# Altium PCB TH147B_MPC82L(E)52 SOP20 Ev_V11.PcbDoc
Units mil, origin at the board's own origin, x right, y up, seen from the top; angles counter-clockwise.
Board outline 2850 x 2110 mil, 2 copper layers (Top Layer, Bottom Layer); 44 components, 39 nets, 228 pads, 82 vias.
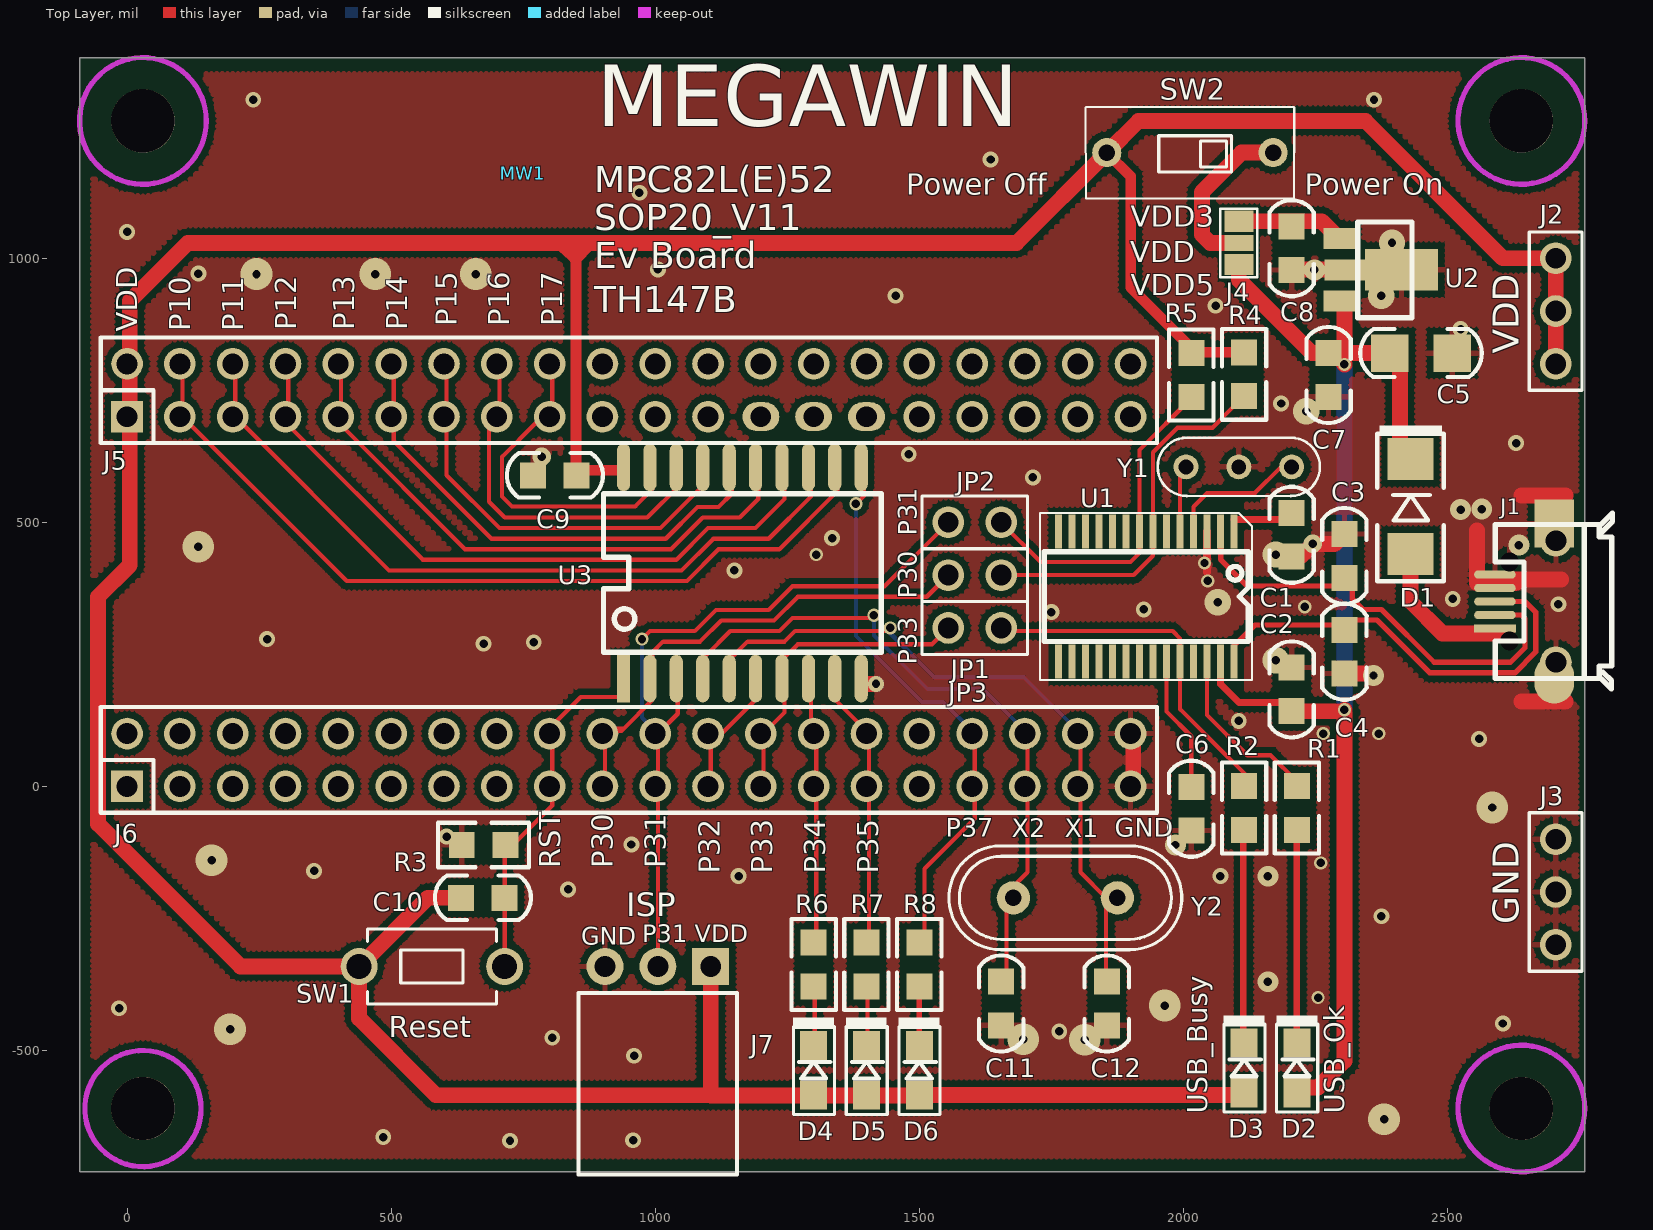
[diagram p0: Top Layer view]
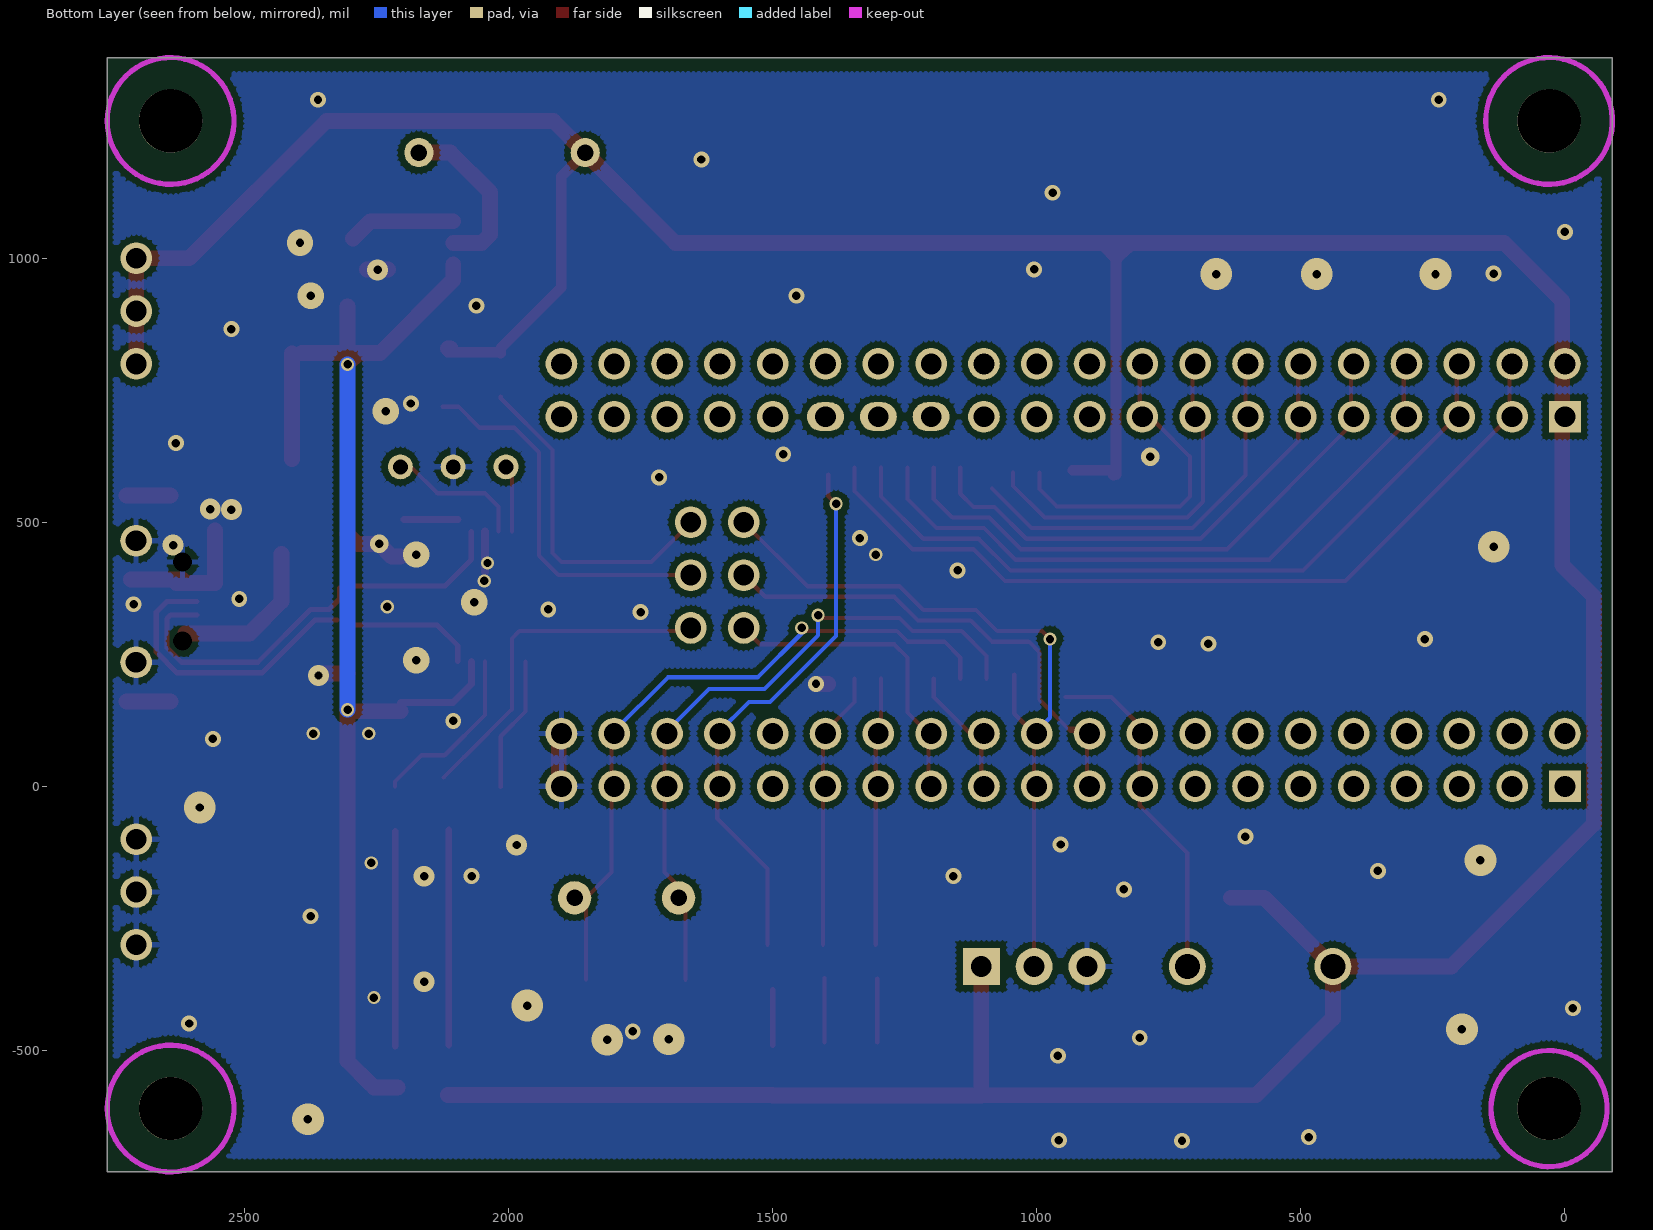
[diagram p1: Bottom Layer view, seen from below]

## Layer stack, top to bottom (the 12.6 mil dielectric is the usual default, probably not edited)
Top Layer: signal copper 1.4
Dielectric: dielectric 12.6, FR-4, Dk 4.8
Bottom Layer: signal copper 1.4

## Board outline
-90,-730 -90,1380 2760,1380 2760,-730

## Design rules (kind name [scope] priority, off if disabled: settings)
Clearance 12 [All] p1 off: gap=12
Clearance 10 [All] p2 off: gap=10
Clearance 6 [All] p3: gap=6
ComponentClearance [All] p1 off: gap=10 collisioncheckmode=3 verticalgap=10 showdistances=FALSE
HoleSize [All] p1: absolutevalues=TRUE maxlimit=500 minlimit=1 maxpercent=80.000 minpercent=20.000
MinimumSolderMaskSliver [All] p1 off: minsoldermaskwidth=10
PolygonConnect VIA [ISVIA] p1: connectstyle=Direct reliefconductorwidth=10 reliefentries=4 polygonreliefangle="90 Angle"
PolygonConnect [All] p2: connectstyle=Relief reliefconductorwidth=10 reliefentries=4 polygonreliefangle="90 Angle"
RoomDefinition "TH147B_MPC82L(E)52 SOP20 Ev_V10" [InComponentClass('TH147B_MPC82L(E)52 SOP20 Ev_V10')] p1: confinementstyle=ConfineIn formatcopy=TRUE lockcomponents=FALSE outline -465,-1240 3115,-1240 3115,1670 -465,1670
RoutingVias [All] p1: holewidth=16 width=25 viastyle="Through Hole" minholewidth=16 minwidth=24 maxholewidth=28 maxwidth=50
SilkToSilkClearance [All] p1 off: silktosilkclearance=10
SilkscreenOverComponentPads [All] p1 off: minsilkscreentomaskgap=10
SolderMaskExpansion [All] p1 off: expansion=4
Width [All] p1: maxlimit=200 minlimit=6 preferedwidth=10
23 further rules are at their usual default settings.

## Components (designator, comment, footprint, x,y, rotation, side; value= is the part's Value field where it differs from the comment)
C1 "4.7uF" 0805C 2205,476.34 r270 top
C2 "0.1uF" 0805C 2205,183.66 r270 top
C3 "15pF" 0805C 2305,436.34 r90 top
C4 "15pF" 0805C 2305,255 r270 top
C5 "4.7uF" 1206C 2450,820.34 r0 top
C6 "0.1uF" 0805C 2015,-42.34 r90 top
C7 "0.1uF" 0805C 2275,779 r270 top
C8 "4.7uF" 0805C 2205,1019 r270 top
C9 "0.1uF" 0805C 810,589 r180 top
C10 "1u" 0805C 673.66,-211 r0 top
C11 "30p" 0805C 1655,-411 r270 top
C12 "30p" 0805C 1855,-411 r270 top
D1 "1N5817" D5817_SMD_1 2430,530 r270 top
D2 "Yellow" 0805D 2215,-533.08 r90 top
D3 "RED" 0805D 2115,-533.08 r90 top
D4 "Green" 0805D 1300,-537.34 r90 top
D5 "RED" 0805D 1400,-537.34 r90 top
D6 "Green" 0805D 1500,-537.34 r90 top
J1 "Micro USB母座" JACK_USB_SMD290X220P065 2590,350 r180 top
J2 "*" PS3P254 2705,800 r90 top
J3 "*" PS3P254 2705,-100 r270 top
J4 "*" JUMP3_SMD 2105,1029 r90 top
J5 "*" PS20X2P254#1 0,700 r0 top locked
J6 "*" PS20X2P254#2 0,0 r0 top locked
J7 "*" PS3P254f_90 1105,-341 r180 top
JP1 "JUMPER2" PS2P254 1555,400 r0 top
JP2 "JUMPER2" PS2P254 1555,500 r0 top
JP3 "JUMPER2" PS2P254 1555,300 r0 top
MW1 "MW-A4" MEGAWIN_T 749.19,1161.19 r0 top
R1 "1K" 0805R 2215,-41 r270 top
R2 "1K" 0805R 2115,-41 r270 top
R3 "47K" 0805R 675,-111 r0 top
R4 "4.7K" 0805R 2115,780.34 r270 top
R5 "4.7K" 0805R 2015,779 r270 top
R6 "1K" 0805R 1300,-337.34 r270 top
R7 "1K" 0805R 1400,-337.34 r270 top
R8 "1K" 0805R 1500,-337.34 r270 top
SW1 "SW TACT-SPST" SW_T_2P 577.21,-341 r180 top
SW2 "-" DIP2_SW 2170,1200 r180 top
U1 "MA101_TSSOP28" TSSOP28_170P065 1929.84,359.52 r180 top
U2 "AIC1734-33(SOT-89)" SOT89 2295,978.06 r270 top
U3 "MPC82L52(20-SOP)" SO20_300P127 1165,404 r0 top locked
Y1 "6MHz" X3P 2205,605 r180 top
Y2 "22.1184MHz" X49U 1776.57,-211 r0 top

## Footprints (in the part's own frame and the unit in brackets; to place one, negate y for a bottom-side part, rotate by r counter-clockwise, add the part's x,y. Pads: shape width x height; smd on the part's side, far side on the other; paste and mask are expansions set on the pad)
0805C [mm]
  rect 1.25x1.25 smd: 1(-1.05,0) 2(1.05,0)
  silkscreen extent -2.31,-1.07 2.31,1.07
0805D [mm]
  rect 1.4x1.3 smd: 1(-1.192,0) 2(1.192,0)
  silkscreen extent -2.12,-1 2.53,0.98
0805R [mm]
  rect 1.25x1.25 smd: 1(-1.05,0) 2(1.05,0)
  silkscreen extent -2.18,-1.07 2.18,1.07
1206C [mm]
  rect 1.8x1.8 smd: 1(-1.5,0) 2(1.5,0)
  silkscreen extent -2.92,-1.15 2.92,1.16
D5817_SMD_1 [mil]
  rect 80x86.61 smd: 1(90,0) 2(-90,0)
  silkscreen extent -153,-63 142,63
DIP2_SW [mm]
  round 1.4 hole 0.8: 1(0,0) 2(8,0)
  silkscreen extent -1.02,-2.2 9.02,2.2
JACK_USB_SMD290X220P065 [mm]
  rect 1.9x1.8 on Mech2: 0(-2.85,-1.15) 0(-2.85,1.15)
  round 0.8 hole 0.9 unplated: 1(-0.7,1.9) 5(-0.7,-1.9)
  rect 2x0.4 smd: 1(0,1.3)
  oval 2x0.4 smd: 2(0,0.65) 3(0,0) 4(0,-0.65) 5(0,-1.3)
  round 1.524 hole 1: 5(-2.931,2.921) 5(-2.931,-2.921)
  oval 1.9x2.3 smd: 5(-2.85,3.75)
  rect 1.9x2.3 smd: 5(-2.85,-3.75)
  silkscreen extent -5.65,-4.25 -0.01,4.2
JUMP3_SMD [mil]
  rect 40x55 smd: 1(-41,0) 3(41,0)
  rect 30x55 smd: 2(0,0)
  silkscreen extent -65,-35 65,35
MEGAWIN_T [mil]
PS2P254 [mil]
  round 60 hole 39.37: 1(0,0) 2(100,0)
  silkscreen extent -50,-50 150,50
PS3P254 [mil]
  round 60 hole 39.37: 1(0,0) 2(100,0) 3(200,0)
  silkscreen extent -50,-50 250,50
PS3P254f_90 [mil]
  rect 70x70 hole 39.37: 1(0,0)
  round 70 hole 39.37: 2(100,0) 3(200,0)
  silkscreen extent -50,50 250,394
PS20X2P254#1 [mil]
  rect 60x60 hole 39.37: 1(0,0)
  round 60 hole 39.37: 2(0,100) 3(100,0) 4(100,100) 5(200,0) 6(200,100) 7(300,0) 8(300,100) 9(400,0) 10(400,100) 11(500,0) 12(500,100) 13(600,0) 14(600,100) 15(700,0) 16(700,100) 17(800,0) 18(800,100) 19(900,0) 20(900,100) 21(1000,0) 22(1000,100) 23(1100,0) 24(1100,100) 26(1200,100) 28(1300,100) 30(1400,100) 31(1500,0) 32(1500,100) 33(1600,0) 34(1600,100) 35(1700,0) 36(1700,100) 37(1800,0) 38(1800,100) 39(1900,0) 40(1900,100)
  oval 70x55 hole 39.37: 25(1200,0) 27(1300,0) 29(1400,0)
  silkscreen extent -50,-50 1950,150
PS20X2P254#2 [mil]
  rect 60x60 hole 39.37: 1(0,0)
  round 60 hole 39.37: 2(0,100) 3(100,0) 4(100,100) 5(200,0) 6(200,100) 7(300,0) 8(300,100) 9(400,0) 10(400,100) 11(500,0) 12(500,100) 13(600,0) 14(600,100) 15(700,0) 16(700,100) 17(800,0) 18(800,100) 19(900,0) 20(900,100) 21(1000,0) 22(1000,100) 23(1100,0) 24(1100,100) 25(1200,0) 26(1200,100) 27(1300,0) 28(1300,100) 29(1400,0) 30(1400,100) 31(1500,0) 32(1500,100) 33(1600,0) 34(1600,100) 35(1700,0) 36(1700,100) 37(1800,0) 38(1800,100) 39(1900,0) 40(1900,100)
  silkscreen extent -50,-50 1950,150
SO20_300P127 [mil]
  rect 25x90 smd: 1(-225,-200)
  oval 25x90 smd: 2(-175,-200) 3(-125,-200) 4(-75,-200) 5(-25,-200) 6(25,-200) 7(75,-200) 8(125,-200) 9(175,-200) 10(225,-200) 11(225,200) 12(175,200) 13(125,200) 14(75,200) 15(25,200) 16(-25,200) 17(-75,200) 18(-125,200) 19(-175,200) 20(-225,200)
  silkscreen extent -263,-150 263,150
SOT89 [mm]
  rect 1.016x1.5 smd: 1(-1.5,0) 3(1.5,0)
  rect 2x3.5 smd: 2(0,3)
  rect 1.016x2.6 smd: 2(0,0.6)
  silkscreen extent -2.3,0.9 2.3,3.5
SW_T_2P [mil]
  round 70 hole 47.24: 1(-137.79,0) 2(137.79,0)
  silkscreen extent -122,-71 122,71
TSSOP28_170P065 [mil]
  rect 13x65 smd: 1(-166.34,-123) 2(-140.75,-123) 3(-115.16,-123) 4(-89.57,-123) 5(-63.98,-123) 6(-38.39,-123) 7(-12.79,-123) 8(12.8,-123) 9(38.39,-123) 10(63.98,-123) 11(89.57,-123) 12(115.16,-123) 13(140.75,-123) 14(166.34,-123) 15(166.34,123) 16(140.75,123) 17(115.16,123) 18(89.57,123) 19(63.98,123) 20(38.39,123) 21(12.8,123) 22(-12.79,123) 23(-38.39,123) 24(-63.98,123) 25(-89.57,123) 26(-115.16,123) 27(-140.75,123) 28(-166.34,123)
  silkscreen extent -200,-158 201,158
X3P [mm]
  round 1.2 hole 0.711: 1(0,0) 2(5.08,0) 3(2.54,0)
  silkscreen extent -1.36,-1.4 6.44,1.4
X49U [mm]
  round 1.6 hole 0.8: 1(-2.5,0) 2(2.5,0)
  silkscreen extent -5.6,-2.5 5.6,2.5

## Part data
C1 C5 C8: library part CAP
C2 C3 C4 C6 C7 C9: library part "CAP NP"
C10: library part C
C11 C12: library part "C NP"
D1: library part DIODE_ZD, "Schottky Diode"
D2 D3 D4 D5 D6: library part LED
J1: library part CON5, "Connector"
J2 J3 J4 J7: library part CON3
J5 J6: library part CON40A
R1 R2 R4 R5 R6 R7 R8: library part R_Dup1
R3: library part R
SW2: library part SW-2
U2: library part AIC1734-33(SOT-89)_0
U3: library part MPC82L52(20-DIP)
Y1: library part CRYSTAL_RC
Y2: library part CRYSTAL

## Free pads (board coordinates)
  round 120 hole 120 unplated: 0(30,-610) 0(30,1260) 0(2640,-610) 0(2640,1260)

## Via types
v1: diameter 30, hole 16, Top Layer to Bottom Layer, tented both sides, 41 vias
v2: diameter 25, hole 16, Top Layer to Bottom Layer, tented both sides, 14 vias
v3: diameter 60, hole 16, Top Layer to Bottom Layer, tented both sides, 11 vias
v4: diameter 50, hole 16, Top Layer to Bottom Layer, tented both sides, 6 vias
v5: diameter 39.37, hole 16, Top Layer to Bottom Layer, tented both sides, 5 vias
v6: diameter 40, hole 16, Top Layer to Bottom Layer, tented both sides, 3 vias
v7: diameter 35, hole 16, Top Layer to Bottom Layer, tented both sides, 2 vias

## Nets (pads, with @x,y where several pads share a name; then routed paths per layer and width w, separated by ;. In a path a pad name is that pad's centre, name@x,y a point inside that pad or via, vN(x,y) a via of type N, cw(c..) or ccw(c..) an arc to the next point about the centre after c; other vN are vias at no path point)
D+: C4.1 J1.3 U1.28 | length 815.5
  Top Layer w10: U1.28 2096.18,266.18 2135.67,305.67 C4.1@2305,305.67 ; C4.1@2325,315 2366.72,315 2466.72,215 2627.72,215 2667,254.28 2667,329.93 2646.93,350 J1.3
D-: C3.1 J1.2 U1.2 | length 831.4
  Top Layer w10: U1.2 2070.59,429.41 2120.63,379.37 C3.1@2305,379.37 ; C3.1@2320,375 2320,355 2340,335 2375,335 2475,235 2619.44,235 2647,262.56 2647,317.84 2640.43,324.41 J1.2
GND_POWER: C1.2 C2.1 C3.2 C4.2 C5.2 C6.1 C7.2 C8.2 C9.2 C11.2 C12.2 J1.4 J1.5 J3.1 J3.2 J3.3 J6.39 J6.40 J7.3 R3.1 U1.3 U2.2 U3.10 Y1.3 | length 837.6
  Top Layer w15: 2045,406 v2@2045,416 ; U1.3 v2@2045,416 ; v2@2046,415 v2@2045,416
  Top Layer w30: U3.10@1395,194 v1(1418,194) ; J6.39@1905,0 J6.40@1905,100 ; C1.2 2221,435 v7(2245,459) 2286.32,459 C3.2 ; C8.2@2228.34,979 U2.2@2268,979 ; C4.2 v5@2349.66,213.66 ; 2555.87,385.05 2629.29,385.05 ; 2555.87,387.64 2555.87,484.72 ; 2618.54,392.05 2715.63,392.05 ; 2640.28,160.87 2723.82,160.87 ; 2640.28,550.87 2723.82,550.87
  other v1: 725,-671 958,-670 485,-664 960,-510 805,-476 1765,-464 2605,-449 -15,-420 2375,-246 835,-195 1158,-170 2070,-170 354,-160 955,-110 605,-95 2560,90 2105,124 675,270 770,273 265,279 1750,330 1925,335 2710,345 2510,355 1150,409 1335,470 1715,585 1480,629 2630,650 2185,725 2525,865.91 2061,910 1455,929 135,971 1005,979 0,1050 970,1124 1635,1187 239,1300 2361,1300
  other v2: 2255,-400 2260,-145 2265,100 2370,100 2230,340 2046,389 2040,423 1305,439
  other v3: 2380,-630 1813,-479.5 1697,-478.83 195,-460 1965,-415 160,-140 2585,-40 135,454 245,970 470,970 660,970
  other v4: 2175,239 2065,349 2175,439 2233,710.5 2375,929 2395,1029
  other v5: 2160,-370 2160,-170 2360,210 2525,524 2565,525
  other v6: 1985,-111 2635.29,456.72 2248,978
  other v7: 785,624
MA101_RX: JP2.2 R5.2 U1.8 | length 636.4
  Top Layer w8: JP2.2 1730,425 1900,425 1917.05,442.05 U1.8 1917.05,637.05 2015,735 R5.2
MA101_TX: JP1.2 R4.2 U1.7 | length 716.9
  Top Layer w8: JP1.2 1906,400 1942.64,436.64 1942.64,632.64 1989,679 2055,679 2095,719 R4.2@2125,719
NetC1_1: C1.1 U1.1 | length 102.5
  Top Layer w13: U1.1@2096.18,505 C1.1@2198.66,505
NetC6_2: C6.2 U1.23 | length 269.1
  Top Layer w8: 1968.23,191.18 1968.23,179 ; U1.23 1968.23,179 ; C6.2 2015,95 1968.23,141.77 1968.23,179
NetD1_1: D1.1 J1.1 | length 297.2
  Top Layer w30: D1.1 2430,350 2490.28,289.72 J1.1@2612.2,289.72
NetD2_2: D2.2 R1.2 | length 407.7
  Top Layer w12: D2.2@2215,-492.66 D2.2 R1.2@2215,-85
NetD3_2: D3.2 R2.2 | length 407.7
  Top Layer w12: D3.2@2113.66,-490 R2.2@2113.66,-82.34
NetD4_2: D4.2 R6.2 | length 120.4
  Top Layer w8: D4.2@1302,-484.67 R6.2@1302,-364.27
NetD5_2: D5.2 R7.2 | length 121.7
  Top Layer w8: D5.2@1402,-484.67 R7.2@1402,-362.93
NetD6_2: D6.2 R8.2 | length 106
  Top Layer w10: D6.2 R8.2@1500,-384.43
NetJ4_2: J4.2 SW2.1 | length 322.7
  Top Layer w30: J4.2 2051,1029 2035,1045 2035,1125 2110,1200 SW2.1
NetU1_4: U1.4 Y1.1 | length 263.8
  Top Layer w8: U1.4 2019.41,529.41 2045,555 2135,555 2185,605 Y1.1
NetU1_5: U1.5 Y1.2 | length 127.1
  Top Layer w8: U1.5 1993.82,593.82 Y1.2
P10: J5.3 J5.4 U3.12 | length 1584.2
  Top Layer w8: J5.4@105,800 105,700 416,389 1060,389 1120,449 1235,449 1345,559 U3.12@1345,604
P11: J5.5 J5.6 U3.13 | length 1423.5
  Top Layer w8: J5.6@205,800 205,700 496,409 1050,409 1110,469 1215,469 1295,549 U3.13@1295,604
P12: J5.7 J5.8 U3.14 | length 1269.3
  Top Layer w8: J5.8@305,800 305,684 560,429 1040,429 1100,489 1190,489 1245,544 U3.14@1245,604
P13: J5.9 J5.10 U3.15 | length 1102.7
  Top Layer w8: J5.10@405,800 405,684 640,449 1030,449 1090,509 1160,509 1195,544 U3.15@1195,604
P14: J5.11 J5.12 U3.16 | length 947.8
  Top Layer w8: J5.12@505,800 505,654 690,469 1020,469 1080,529 1120,529 1145,554 U3.16@1145,604
P15: J5.13 J5.14 U3.17 | length 763.5
  Top Layer w8: J5.14@605,800 605,589 705,489 1010,489 U3.17@1085,564
P16: J5.15 J5.16 U3.18 | length 700.6
  Top Layer w8: J5.15@705,700 J5.15@705,709 ; J5.16@705,800 J5.15@705,709 ; U3.18@1045,594 1045,569 985,509 715,509 685,539 685,689 J5.15@705,709
P17: J5.17 J5.18 U3.19 | length 646.3
  Top Layer w8: J5.17@805,700 J5.18@805,800 ; J5.17@817.5,687.5 773.5,687.5 710,624 710,549 729,530 962,530 995,563 U3.19@995,594
P30_RXD: J6.19 J6.20 JP1.1 U3.2 | length 956.9
  Top Layer w8: J6.19@905,0 905,100 J6.20@916,100 ; J6.20@910,105 936,105 940,109 ; J6.20@914,109 940,109 ; JP1.1 1514,359 1270,359 1225,314 1125,314 1085,274 1015,274 995,254 995,164 940,109
P31_TXD: J6.21 J6.22 J7.2 JP2.1 U3.3 | length 1536.1
  Top Layer w8: v2(975,279) 990,294 1075,294 1115,334 1215,334 1260,379 1434,379 JP2.1 ; 1005,-236 J7.2 1005,100 1042.6,137.6 U3.3@1042.6,211.6
  Bottom Layer w8: v2(975,279) 975,130 J6.22@1005,100
P32: J6.23 J6.24 U3.6 | length 264.6
  Top Layer w8: J6.23@1105,0 J6.24@1105,100 ; J6.24@1116,100 J6.24@1105,100 ; U3.6@1195,204 1195,169 1126,100 J6.24@1105,100
P33: J6.25 J6.26 JP3.1 U3.7 | length 594.8
  Top Layer w8: J6.25@1205,0 1205,100 1245,140 1245,244 1270,269 1524,269 JP3.1 ; J6.26@1225,99 J6.26@1225,100
P34: J6.27 J6.28 R6.1 U3.8 | length 505
  Top Layer w8: J6.28@1295,99 U3.8@1295,204 ; R6.1@1305,-300 1305,0 J6.28@1305,100
P35: J6.29 J6.30 R7.1 U3.9 | length 548.9
  Top Layer w8: U3.9@1345,204 1345,160 J6.30@1405,100 ; J6.30@1385,100 J6.30 J6.30@1405,100 ; R7.1@1405,-300 J6.30@1405,100
P37: J6.33 J6.34 R8.1 U3.11 | length 1061.2
  Top Layer w8: v2(1380,535) 1395,550 U3.11@1395,590 ; R8.1@1510,-300 1510,-156 1605,-61 J6.34@1605,109
  Bottom Layer w8: v2(1380,535) 1380,285 1505,160 1545,160 J6.34@1605,100
RST: C10.2 J6.17 J6.18 R3.2 SW1.1 U3.1 | length 696.7
  Top Layer w8: SW1.1 C10.2 715,-126 805,-36 805,115 859,169 ; 830,140 859,169 ; U3.1@945,169 859,169
USB_BUSY: JP3.2 R2.1 U1.24 | length 860.2
  Top Layer w8: JP3.2@1655,294 1785,294 ; 1715,294 1785,294 ; 2085,55 1993.82,146.18 ; R2.1@2123,17 1993.82,146.18 ; 1785,294 1980,294 1993.82,280.18 U1.24 1993.82,146.18
USB_OK: R1.1 U1.26 | length 344.6
  Top Layer w8: 2045,191.18 2045,179 ; U1.26 2045,179 ; R1.1 2215,9 2165,59 2121,59 2045,135 2045,179
VDD: C9.1 C10.1 D3.1 D4.1 D5.1 D6.1 J2.1 J2.2 J2.3 J5.1 J5.2 J7.1 R4.1 R5.1 SW1.2 SW2.2 U3.20 | length 8263.6
  Top Layer w15: 785,1029 790,1034 ; 817,1025 826.5,1015.5 827.01,1015.5 846.5,996.01 846.5,995.5 850,992 ; 850,995 880,1025
  Top Layer w20: C9.1@850,590 C9.1@850,599 ; 850,1020.5 850,995 850,992 C9.1@850,599 ; C9.1@855,589 C9.1@855,599 ; U3.20@932,599 C9.1@855,599 ; SW2.2 1900,1155.04 1900,945 2015,830 R5.1 ; R5.1@2016.34,821.68 R4.1 ; C9.1@850,599 C9.1@855,599
  Top Layer w30: C10.1 569.41,-211 SW1.2 ; J7.1 1105,-584.9 ; D4.1@1300,-585 1105,-585 1105,-584.9 ; D4.1@1305,-585 D5.1@1400,-585 ; D5.1@1405,-585 D5.1@1400,-585 ; D6.1@1500,-585 D5.1@1400,-585 ; D6.1 D3.1@2115,-584.26 ; R4.1@2109.95,829 R4.1@2115,829 ; J2.1 J2.2 J2.3 2605,1000 2345,1260 1915.04,1260 SW2.2 1684.04,1029 785,1029 115,1029 5,919 5,419 -55,359 -55,-71 215,-341 SW1.2 ; SW1.2 439.41,-439.31 585,-584.9 1105,-584.9
VDD3: C8.1 J4.3 U2.1 | length 203.6
  Top Layer w30: J4.3 2262.11,1070 U2.1
VDD5: C2.2 C5.1 C7.1 D1.2 D2.1 J4.1 U1.27 U2.3 | length 2406.8
  Top Layer w13: U1.27 2070.59,193.41 2105,159 C2.2@2205,159
  Top Layer w30: J4.1 2105,959 2243.66,820.34 C7.1@2273.66,820.34 ; C2.2 2302.32,142.32 v2(2305,145) ; D2.1@2210,-570 2255,-570 ; 2260,-565 2305,-520 v2@2305,139.64 ; C7.1@2274.33,819.67 C7.1@2273.66,820.34 ; v2(2305,799) 2305,800.34 C7.1@2285,820.34 ; U2.3@2305,909 2305,820.34 ; C5.1 2305,820.34 ; D1.2@2410,620 C5.1@2410,820 ; C7.1@2273.66,820.34 C7.1 C7.1@2285,820.34 ; C7.1@2285,820.34 2305,820.34
  Bottom Layer w30: v2(2305,145) v2(2305,799)
XTAL1: C12.1 J6.37 J6.38 U3.5 Y2.2 | length 1294.6
  Top Layer w8: U3.5@1145,204 1145,244 1175,274 1245,274 1265,294 v2@1445,294 ; J6.38@1805,100 1805,-162.58 1853.66,-211.24 C12.1@1853.66,-365
  Bottom Layer w8: v2(1445,300) 1445,290 1528.5,206.5 1698.5,206.5 J6.38@1805,100
XTAL2: C11.1 J6.35 J6.36 U3.4 Y2.1 | length 1266.8
  Top Layer w8: U3.4@1095,204 1095,247 1142,294 1235,294 1260,319 v2@1414,319 ; C11.1@1665,-366 Y2.1@1665,-212.85 ; Y2.1@1667.36,-200.21 1705,-162.58 J6.36@1705,100
  Bottom Layer w8: v2(1414,324) 1414,286 1515.71,184.29 1620.71,184.29 J6.36@1705,100
pads on no net: J1.0 J5.19 J5.20 J5.21 J5.22 J5.23 J5.24 J5.25 J5.26 J5.27 J5.28 J5.29 J5.30 J5.31 J5.32 J5.33 J5.34 J5.35 J5.36 J5.37 J5.38 J5.39 J5.40 J6.1 J6.2 J6.3 J6.4 J6.5 J6.6 J6.7 J6.8 J6.9 J6.10 J6.11 J6.12 J6.13 J6.14 J6.15 J6.16 J6.31 J6.32 U1.6 U1.9 U1.10 U1.11 U1.12 U1.13 U1.14 U1.15 U1.16 U1.17 U1.18 U1.19 U1.20 U1.21 U1.22 U1.25

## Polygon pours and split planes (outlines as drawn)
GND_POWER on Bottom Layer "Bottom Layer-No Net" (hatched 90Degree grid 10 track 10, remove dead copper, pour order 1001): -65,-701 2745,-701 2745,1350 -65,1350
GND_POWER on Top Layer "Bottom Layer-No Net" (hatched 90Degree grid 10 track 10, remove dead copper, pour order 1001): -65,-701 2745,-701 2745,1350 -65,1350

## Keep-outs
Keep-Out Layer:
  circle w10: c2640,-610 r120
  circle w10: c30,1260 r120
  circle w10: c30,-610 r110
  circle w10: c2640,1260 r120

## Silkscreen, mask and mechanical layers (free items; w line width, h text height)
Top Overlay:
  text "MPC82L(E)52" at 884.19,1125.19 h50
  text "Power Off" at 1475,1120 h40
  text "Power On" at 2230,1120 h40
  text "VDD3" at 1900,1060 h40
  text "SOP20_V11" at 885,1053 h50
  text "VDD" at 1899.25,992 h40
  text "Ev Board" at 885,981 h50
  text "VDD5" at 1900,930 h40
  text "TH147B" at 885,898 h50
  text "P15" at 623.95,870.95 h40 r90
  text "P16" at 723.95,870.95 h40 r90
  text "P17" at 823.95,870.95 h40 r90
  text "P12" at 320,864 h40 r90
  text "P13" at 430,864 h40 r90
  text "P14" at 530,864 h40 r90
  text "P10" at 120,862 h40 r90
  text "P11" at 220,862 h40 r90
  text "VDD" at 19,861 h40 r90
  text "VDD" at 2635,819 h50 r90
  text "P31" at 1495,475 h35 r90
  text "P30" at 1495,355 h35 r90
  text "P33" at 1495,230 h35 r90
  text "P37" at 1550,-95 h35
  text "GND" at 1870,-95 h35.43
  text "X2" at 1675,-96 h35
  text "X1" at 1775,-96 h35.43
  text "RST" at 820,-155 h40 r90
  text "P30" at 920,-155 h40 r90
  text "P31" at 1020,-155 h40 r90
  text "P32" at 1122,-165 h40 r90
  text "P33" at 1222,-165 h40 r90
  text "P34" at 1322,-165 h40 r90
  text "P35" at 1422,-165 h40 r90
  text "ISP" at 945,-246 h45
  text "GND" at 2635,-261 h50 r90
  text "P31" at 975,-295 h33
  text "VDD" at 1075,-295 h33
  text "GND" at 860,-300 h33
  text "Reset" at 495,-475 h40
  text "USB_Busy" at 2045,-620 h38 r90
  text "USB_Ok" at 2305,-620 h38 r90
Mechanical 1:
  the board outline again, w13

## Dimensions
-90,-730 to 2760,-730 on Top Overlay
-90,1380 to -90,-730 on Top Overlay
